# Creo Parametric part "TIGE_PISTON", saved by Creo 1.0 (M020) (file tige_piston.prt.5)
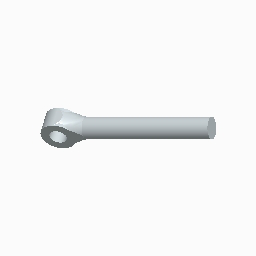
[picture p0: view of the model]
Units: millimeter Newton Second (mmNs); MM, TONNE, SECS
Materials in the file: FE20

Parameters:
  PTC_MATERIAL_NAME = "FE20"

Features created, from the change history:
  datum axis "A_1"
  datum axis "A_2"
  datum plane "DTM1"
  datum point "PNT0"

Other named items: TIGE_PISTON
